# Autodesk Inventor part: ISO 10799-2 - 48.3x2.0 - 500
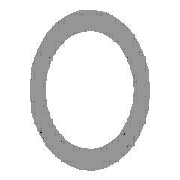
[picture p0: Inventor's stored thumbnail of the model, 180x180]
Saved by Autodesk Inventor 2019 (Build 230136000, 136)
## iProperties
IsCustomPart: 1
Created: 2018-07
Part Number: ISO 10799-2 - 48.3x2.0 - 500
Material: Acier, doux
Description: Aciers de construction - Coupes creuses profilées formées à froid, soudées
Document SubType Name: Modeling
Standard: ISO
Designer: Fabian Perrée
Standard Revision: First edition 2011-09-15
Standards Organization: ISO
Language: fr-FR
Size Designation: 48.3x2.0
Categories: <MemberInstance><Categories><Category DisplayName="Profilés" InternalName="089c4875-fa83-4c05-b084-43b9cc11f5ed" Mnemonic="GRDR"><CategoryParameter DisplayName=
Stock Number: 48.3x2.0
Density: 7.85 g/cm^3
Appearance: Semi-poli
Mass: 1065.61 g
Surface Area: 1369.22 cm^2
Volume: 135.746 cm^3
_CCFamilyMember: 14
_CCFamilyDisplayName: ISO 10799-2 (Profils creux circulaires - Formés à froid) - Aciers de construction - Coupes creuses profilées formées à froid, soudées
_FrameMemberDoc: Frame Member File
_Version: 15.0.0
_GetPNFromCC: 1
G_L: 500,000 mm
G_W: 48,300 mm
G_H: 48,300 mm
+44A61AB8-31B7-4BA9-AADA-19D1380BA286+DETAILDECOUPE1: Grugeage
+8A7669E2-ED20-4943-939F-184320856275+DETAILDECOUPE2: Grugeage
Author: Fabian Perrée
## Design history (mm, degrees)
node "Plan de départ"
node "Plan de fin"
sketch "Esquisse"
  geometry: C1 r 22.15 at (0, 0); C2 r 24.15 at (0, 0); 2 further points
  constraints: 3 coincident, 2 centre point
  dimensions: "d0" = 48.3 diameter of C2 (= G_H); "d1" = 2 radial gap between concentric circles of C2 C1 (= G_T)
extrude "Corps" new body sketch "Esquisse" stored distance "d2" = 500 (= G_L); taper "d3" = 0 deg
node "Driven Length"
  sketch "Sketch3"
    geometry: L1 (0, 0)-(10, 0) reference
    constraints: 2 end point, 1 horizontal
  workplane "Work Plane3"
  sketch "Sketch4"
    geometry: L1 (-2, 0)-(12, 0) reference; L2 (-2, 500)-(12, 500) reference
    dimensions: "d7" = 500 distance between parallel lines of L1 L2 (derived)
body "Solid1"
feature "Sculpter1"
feature "Combiner1"
feature "Sculpter3"
feature "Combiner3"
body "Srf11"
body "Srf12"
node "Solide5"
body "Srf14"
body "Srf15"
node "Solide6"
feature "Surface1"
body "Srf10"
feature "Carreau délimité7" dims "d20" = 5, "d21" = 0
feature "Carreau délimité8" dims "d22" = 5, "d23" = 0
feature "Surface3"
body "Srf13"
feature "Carreau délimité9" dims "d24" = 5, "d25" = 0
feature "Carreau délimité10" dims "d26" = 5, "d27" = 0
other parameters: "G_H" = 48.3 [user parameter; used in 1 equation term], "G_T" = 2 [user parameter; used in 1 equation term], "G_L" = 500 (= d7) [user parameter; used in 1 equation term], "G_OFFSET_START" = 0 [user parameter; used in 1 equation term], "G_OFFSET_END" = 0 [user parameter; used in 1 equation term], "d4" = 0 (computed from G_OFFSET_START), "d5" = 500 (= G_OFFSET_END + B_L), "B_L" = 500 [user parameter; used in 1 equation term], "d6" = 90 deg, "MAS" = 0.228 [user parameter]
